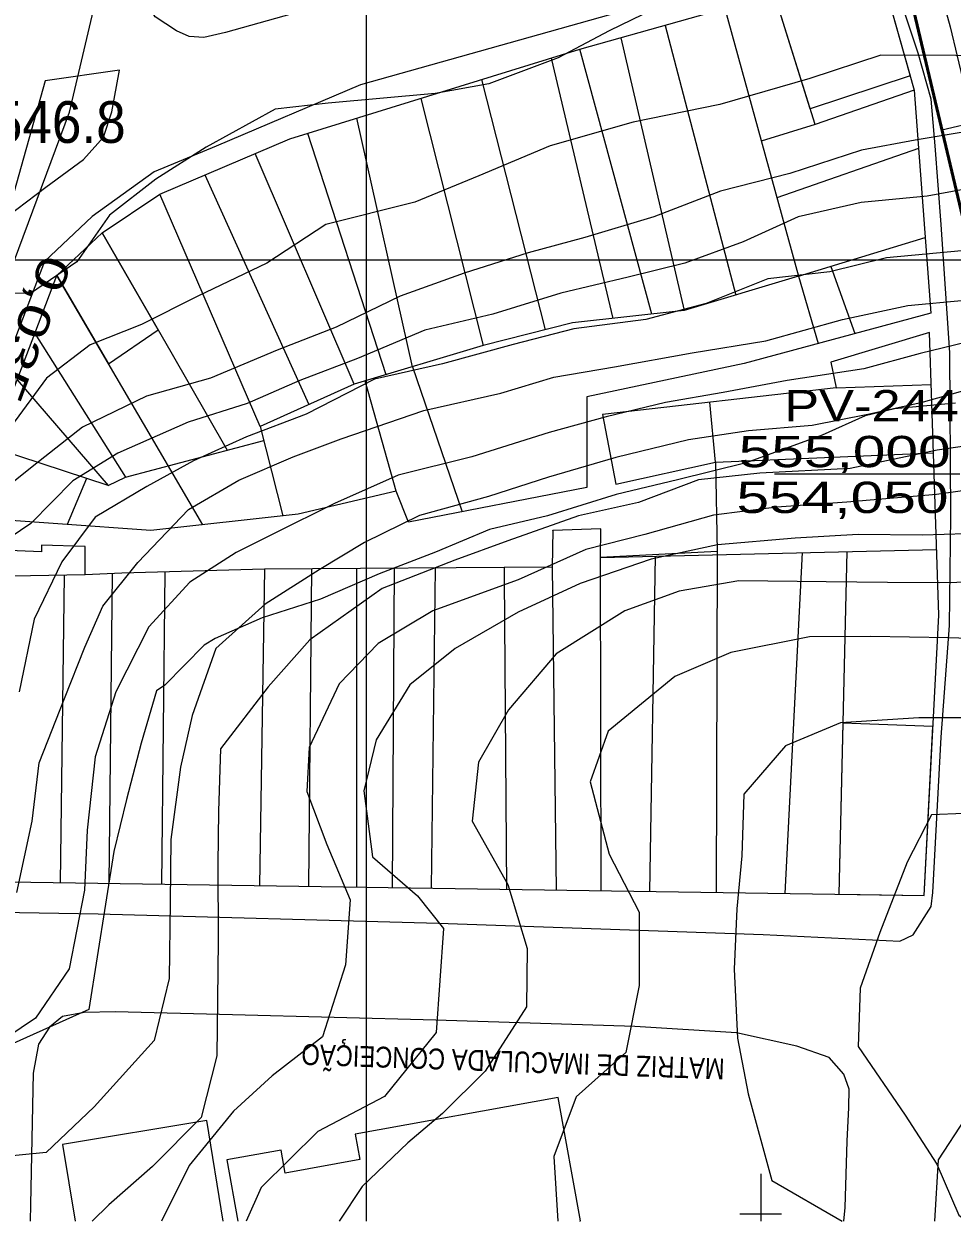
# Model space of a CAD drawing. Extents: x 949 to 2631, y -1701 to -513.
# Drawn here: x 1266.8 to 1355.6, y -912.7 to -798 of the extents above; entities that cross this region are included whole.
import ezdxf

# ---------------------------------------------------------------- set-up
doc = ezdxf.new("R2010")
doc.units = 0
doc.header["$LTSCALE"] = 1.2
for name, color, linetype, lineweight in [('10', 7, 'Continuous', 13), ('11', 7, 'Continuous', 13), ('19', 7, 'Continuous', 13), ('21', 7, 'Continuous', 13), ('29', 7, 'Continuous', 25), ('3', 7, 'Continuous', 13), ('32', 7, 'Continuous', 13), ('33', 7, 'Continuous', 25), ('34', 7, 'Continuous', 35), ('4', 7, 'Continuous', 13), ('5', 7, 'Continuous', 13), ('8', 7, 'Continuous', 13)]:
    doc.layers.add(name, color=color, linetype=linetype, lineweight=lineweight)
doc.layers.add('14', color=7, linetype='Continuous')

msp = doc.modelspace()

# ---------------------------------------------------------------- linework, layer by layer
at = {"layer": '10'}
for p, q in [((1328.142, -798.142), (1334.922, -823.972)), ((1323.902, -799.332), (1329.972, -825.462)), ((1317.232, -801.292), (1323.162, -826.212)), ((1326.872, -825.802), (1320.002, -800.432)), ((1316.692, -827.302), (1310.612, -803.332)), ((1304.772, -805.132), (1310.732, -828.812)), ((1303.972, -830.832), (1298.632, -807.022)), ((1342.512, -807.622), (1337.362, -809.222)), ((1293.912, -808.472), (1301.402, -831.592)), ((1352.412, -809.922), (1338.852, -814.672)), ((1284.082, -812.462), (1294.042, -834.452)), ((1289.382, -836.552), (1279.762, -814.312)), ((1283.892, -845.982), (1269.922, -822.102)), ((1340.912, -822.172), (1342.822, -828.602)), ((1344.032, -821.222), (1346.312, -827.662)), ((1303.972, -830.832), (1308.732, -844.722)), ((1302.402, -842.752), (1299.422, -832.192)), ((1344.542, -832.862), (1353.622, -832.552)), ((1332.992, -839.992), (1332.432, -834.232)), ((1274.812, -842.222), (1263.632, -838.542)), ((1332.992, -839.992), (1353.842, -839.092)), ((1272.752, -841.542), (1270.912, -845.952)), ((1333.122, -848.522), (1333.042, -881.202)), ((1345.562, -848.542), (1344.782, -881.372)), ((1326.692, -881.102), (1327.222, -848.982)), ((1339.652, -881.302), (1341.312, -848.642)), ((1270.622, -850.812), (1270.232, -880.242)), ((1275.212, -850.652), (1274.882, -880.312)), ((1280.242, -850.502), (1279.932, -880.392)), ((1289.782, -850.232), (1289.302, -880.532)), ((1294.292, -850.202), (1294.022, -880.602)), ((1298.642, -880.672), (1298.632, -850.172)), ((1302.212, -850.152), (1302.032, -880.732)), ((1306.122, -850.122), (1305.762, -880.782)), ((1317.352, -850.052), (1317.732, -880.962))]:
    msp.add_line(p, q, dxfattribs=at)
for points in [[(1261.072, -845.232), (1267.812, -827.642), (1269.922, -822.102), (1274.252, -818.022), (1279.762, -814.312), (1292.232, -808.992), (1320.002, -800.432), (1348.632, -792.352), (1351.992, -804.332), (1353.582, -825.712), (1335.712, -830.512), (1320.662, -833.722), (1320.662, -842.402), (1303.592, -845.722), (1302.402, -842.752), (1293.012, -844.962), (1278.902, -846.532)], [(1256.682, -880.042), (1352.952, -881.502), (1354.362, -854.642), (1353.462, -827.572), (1344.032, -830.402), (1344.542, -832.862), (1322.142, -835.402), (1323.442, -842.082), (1332.992, -839.992), (1333.122, -848.522), (1321.962, -849.102), (1321.992, -846.352), (1317.392, -846.522), (1317.392, -846.502), (1317.352, -850.052), (1289.782, -850.232), (1276.142, -850.612), (1272.622, -850.772), (1272.632, -848.042), (1268.442, -847.922), (1268.432, -848.582), (1259.812, -848.222), (1257.372, -854.062), (1257.092, -864.242)]]:
    msp.add_lwpolyline(points, close=True, dxfattribs=at)
for points in [[(1351.992, -804.332), (1342.512, -807.622), (1338.622, -795.182)], [(1333.882, -796.512), (1340.912, -822.172), (1353.042, -818.472)], [(1340.912, -822.172), (1329.972, -825.462), (1319.292, -826.642), (1310.732, -828.812), (1298.392, -832.492), (1288.892, -810.412)], [(1274.252, -818.022), (1280.812, -829.402), (1286.232, -838.832)], [(1267.812, -827.642), (1276.482, -841.402), (1289.722, -837.902)], [(1266.112, -832.082), (1274.812, -842.222), (1276.482, -841.402)], [(1298.392, -832.492), (1289.382, -836.552), (1291.552, -845.122)], [(1322.022, -881.032), (1321.962, -849.102), (1354.152, -848.342)], [(1272.622, -850.772), (1262.132, -850.962), (1261.222, -880.112)], [(1312.982, -880.892), (1312.772, -851.042), (1312.782, -850.082)]]:
    msp.add_lwpolyline(points, dxfattribs=at)
at = {"layer": '11'}
for points in [[(1351.612, -802.972), (1342.042, -806.132), (1338.622, -795.182), (1348.632, -792.352)], [(1269.922, -822.102), (1274.872, -830.572), (1279.602, -827.312), (1274.252, -818.022)], [(1352.952, -881.502), (1353.802, -865.292), (1345.172, -864.982), (1344.782, -881.372)]]:
    msp.add_lwpolyline(points, close=True, dxfattribs=at)
for points in [[(1319.991, -912.671), (1320.042, -912.662), (1317.912, -900.842), (1298.482, -904.342), (1298.922, -906.782), (1291.772, -908.072), (1291.382, -905.872), (1286.182, -906.802), (1287.239, -912.671)], [(1285.842, -912.671), (1284.262, -903.052), (1270.442, -905.322), (1271.649, -912.671)]]:
    msp.add_lwpolyline(points, dxfattribs=at)
at = {"layer": '19'}
for p, q in [((1337.316, -908.149), (1337.312, -912.671)), ((1339.308, -912.02), (1335.301, -912.013))]:
    msp.add_line(p, q, dxfattribs=at)
at = {"layer": '21'}
for p, q in [((1299.562, -912.671), (1299.562, -607.115)), ((1438.974, -820.632), (1228.032, -820.632))]:
    msp.add_line(p, q, dxfattribs=at)
at = {"layer": '29'}
msp.add_line((1354.651, -808.143), (1358.377, -807.261), dxfattribs=at)
at = {"layer": '29', "lineweight": 53}
msp.add_lwpolyline([(1073.88, -805.132), (1073.202, -806.436), (1075.81, -807.79), (1086.799, -786.637), (1101.557, -787.729), (1138.256, -763.647), (1228.052, -719.585), (1284.057, -691.479), (1304.502, -688.949), (1348.513, -782.198), (1360.795, -834.118)], dxfattribs=at)
at = {"layer": '29'}
msp.add_lwpolyline([(1086.799, -786.637), (1101.557, -787.729), (1138.256, -763.647), (1228.052, -719.585), (1284.057, -691.479), (1304.502, -688.949), (1348.513, -782.198), (1360.795, -834.118), (1364.521, -833.237)], dxfattribs=at)
at = {"layer": '32'}
msp.add_lwpolyline([(1254.721, -881.197), (1256.541, -845.637), (1271.121, -806.437), (1289.341, -728.947), (1285.701, -694.297)], dxfattribs=at)
at = {"layer": '33'}
msp.add_line((1356.371, -841.118), (1338.63, -841.118), dxfattribs=at)
at = {"layer": '4'}
for points in [[(1378.512, -810.802), (1376.852, -811.492), (1372.742, -812.462), (1371.602, -812.732), (1365.112, -813.192), (1359.652, -813.332), (1353.232, -814.502), (1346.912, -815.092), (1340.882, -816.492), (1335.632, -818.862), (1330.042, -820.902), (1324.622, -822.252), (1318.182, -823.782), (1311.642, -825.812), (1305.142, -827.332), (1298.702, -830.042), (1293.182, -832.152), (1288.132, -834.362), (1282.492, -836.142), (1275.742, -839.122), (1271.452, -841.772), (1267.422, -845.862), (1262.442, -849.192)], [(1355.959, -834.334), (1350.117, -834.879), (1347.319, -835.529), (1343.185, -837.395), (1335.903, -840.053), (1329.35, -841.685), (1323.464, -843.083), (1316.89, -845.124), (1311.341, -846.421), (1306.153, -848.605), (1300.766, -850.664), (1295.171, -853.112), (1289.562, -854.883), (1285.08, -856.861), (1284.009, -857.523), (1280.235, -861.353), (1279.445, -861.881), (1277.993, -866.881), (1276.575, -872.302), (1275.369, -877.269), (1272.977, -892.4), (1252.838, -901.45)], [(1360.162, -837.972), (1354.212, -838.822), (1345.862, -840.582), (1337.232, -841.042), (1331.352, -841.662), (1325.612, -843.842), (1319.872, -845.122), (1313.102, -847.502), (1308.022, -849.362), (1301.072, -852.072), (1294.122, -856.982), (1290.152, -861.512), (1285.592, -867.432), (1285.392, -873.422), (1285.332, -878.482), (1285.352, -885.782), (1285.292, -891.442), (1285.222, -896.852), (1283.722, -902.762), (1279.072, -907.452), (1274.902, -911.122), (1273.29, -912.671)], [(1359.682, -864.482), (1352.432, -864.472), (1344.942, -864.942), (1339.682, -867.152), (1335.702, -871.782), (1335.502, -877.672), (1335.032, -882.772), (1334.762, -888.532), (1335.072, -895.152), (1336.102, -900.472), (1338.382, -908.792), (1345.114, -912.671)]]:
    msp.add_lwpolyline(points, dxfattribs=at)
at = {"layer": '5'}
for points in [[(1329.252, -795.492), (1322.782, -798.662), (1317.922, -801.252), (1311.282, -803.732), (1306.142, -804.662), (1295.892, -805.592), (1290.812, -806.172), (1284.202, -809.792), (1279.392, -812.872), (1274.942, -816.322), (1271.822, -820.802), (1267.402, -823.812), (1260.302, -823.682)], [(1373.102, -797.892), (1368.652, -800.522), (1361.762, -801.052), (1355.992, -801.032), (1348.812, -800.982), (1342.002, -803.242), (1333.392, -805.722), (1325.082, -807.412), (1317.142, -809.692), (1310.312, -812.552), (1304.182, -815.082), (1295.672, -817.222), (1290.022, -820.902), (1283.402, -824.092), (1278.002, -826.792), (1273.092, -828.752), (1268.922, -831.942), (1265.482, -836.612)], [(1359.942, -807.822), (1352.102, -809.122), (1346.952, -810.102), (1340.082, -812.312), (1333.462, -814.032), (1327.082, -816.482), (1320.452, -818.452), (1315.052, -819.922), (1308.922, -821.882), (1302.782, -824.092), (1296.652, -827.042), (1291.002, -829.242), (1284.622, -831.942), (1278.492, -833.662), (1272.352, -836.612), (1267.692, -840.292), (1262.782, -844.212)], [(1359.282, -819.482), (1349.352, -820.392), (1343.932, -821.742), (1338.002, -822.422), (1332.072, -824.792), (1326.312, -826.322), (1319.422, -827.202), (1313.612, -828.692), (1306.852, -830.552), (1300.342, -832.042), (1293.772, -835.382), (1288.062, -837.542), (1283.002, -839.842), (1278.542, -842.322), (1273.572, -845.232), (1270.402, -849.532), (1267.742, -855.022), (1266.312, -861.992)], [(1266.082, -881.212), (1267.542, -874.362), (1268.222, -868.782), (1270.642, -862.622), (1272.602, -857.712), (1274.322, -853.782), (1277.662, -849.602), (1282.512, -844.502), (1287.332, -841.702), (1292.532, -839.472), (1297.122, -837.742), (1305.042, -835.022), (1312.412, -833.372), (1317.482, -831.852), (1323.312, -830.842), (1330.732, -829.502), (1337.812, -828.342), (1345.122, -826.322), (1351.392, -824.962), (1356.852, -824.452)], [(1359.262, -827.932), (1352.582, -829.562), (1347.172, -831.052), (1339.852, -832.162), (1333.702, -833.312), (1328.202, -834.272), (1322.512, -835.632), (1317.062, -837.122), (1309.632, -839.472), (1302.592, -841.232), (1296.492, -843.942), (1290.732, -846.822), (1287.082, -848.642), (1282.632, -851.482), (1278.732, -855.752), (1275.552, -861.972), (1273.582, -868.202), (1272.812, -875.242), (1272.572, -880.982), (1271.102, -888.522), (1267.862, -893.232), (1262.452, -896.892)], [(1359.362, -832.422), (1352.652, -834.282), (1347.562, -835.422), (1342.242, -836.482), (1336.142, -836.992), (1330.382, -837.842), (1323.432, -839.532), (1316.992, -841.402), (1311.232, -843.262), (1304.642, -845.092), (1299.372, -847.682), (1295.032, -850.292), (1289.862, -853.592), (1285.142, -857.832), (1282.852, -864.232), (1281.742, -869.192), (1280.822, -876.132), (1280.752, -882.102), (1280.662, -889.422), (1279.222, -895.382), (1273.472, -901.742), (1268.882, -906.102), (1263.692, -906.602)], [(1360.282, -842.202), (1354.132, -843.082), (1345.542, -843.812), (1338.852, -844.282), (1332.792, -845.042), (1326.222, -846.902), (1320.552, -848.342), (1314.082, -851.242), (1305.912, -854.212), (1300.692, -857.352), (1296.952, -861.212), (1294.072, -867.302), (1293.862, -871.532), (1295.762, -876.602), (1297.982, -881.892), (1297.562, -888.132), (1295.332, -895.012), (1290.512, -898.752), (1286.822, -902.132), (1282.572, -907.362), (1279.945, -912.671)], [(1359.012, -846.792), (1352.812, -846.972), (1346.632, -846.892), (1340.592, -847.272), (1333.162, -847.892), (1326.822, -849.262), (1320.032, -851.612), (1314.082, -854.332), (1308.062, -857.822), (1303.712, -861.292), (1300.482, -866.582), (1299.302, -871.452), (1300.122, -877.782), (1304.442, -881.512), (1306.922, -884.632), (1306.222, -894.612), (1301.282, -900.742), (1294.912, -904.092), (1289.472, -909.472), (1288.044, -912.671)], [(1359.322, -851.452), (1354.472, -851.532), (1349.442, -851.502), (1343.572, -851.452), (1335.222, -851.332), (1329.492, -852.332), (1324.292, -854.212), (1317.732, -858.342), (1313.152, -863.702), (1310.282, -868.722), (1309.662, -874.382), (1313.082, -880.442), (1314.952, -886.562), (1314.892, -892.152), (1310.912, -898.302), (1306.822, -902.382), (1303.532, -905.182), (1299.142, -909.372), (1296.94, -912.671)], [(1362.292, -857.042), (1355.282, -856.802), (1347.822, -856.682), (1341.972, -856.722), (1334.432, -858.212), (1329.092, -860.522), (1322.702, -865.752), (1320.982, -870.612), (1322.792, -877.522), (1325.662, -883.092), (1325.682, -890.112), (1324.382, -896.532), (1319.642, -900.782), (1317.482, -906.502), (1317.887, -912.671)], [(1438.974, -884.394), (1433.602, -881.622), (1422.692, -878.042), (1417.792, -876.432), (1409.672, -874.162), (1403.702, -872.502), (1397.722, -871.112), (1389.032, -869.382), (1381.082, -868.732), (1375.252, -868.652), (1369.022, -869.382), (1359.862, -873.512), (1353.672, -873.752), (1351.322, -878.292), (1348.722, -885.022), (1346.842, -890.362), (1346.622, -895.952), (1351.142, -902.512), (1354.172, -907.222), (1356.262, -912.122), (1357.054, -912.671)]]:
    msp.add_lwpolyline(points, dxfattribs=at)
at = {"layer": '8'}
for points in [[(1336.322, -745.502), (1347.332, -772.682), (1349.352, -777.042), (1350.432, -778.482), (1351.772, -779.272), (1353.892, -779.292), (1389.292, -768.962), (1393.382, -768.602), (1397.262, -768.472), (1399.172, -775.642), (1366.552, -784.062), (1353.192, -789.082), (1353.182, -790.002), (1355.462, -798.272), (1360.132, -817.952), (1363.272, -828.742), (1363.812, -830.352), (1364.322, -831.052), (1365.312, -831.522), (1372.842, -831.172), (1410.152, -827.372), (1438.974, -824.574)], [(1331.712, -746.692), (1345.172, -778.472), (1345.822, -779.662), (1345.682, -780.902), (1343.832, -781.952), (1311.812, -791.562), (1286.072, -798.812), (1283.992, -799.302), (1282.572, -799.202), (1281.372, -798.652), (1279.322, -797.332), (1278.822, -796.482)], [(1258.762, -883.002), (1273.872, -883.252), (1306.462, -884.142), (1337.542, -885.222), (1350.632, -885.862), (1351.892, -885.242), (1353.632, -882.532), (1353.772, -881.202), (1354.582, -866.332), (1355.372, -855.622), (1355.502, -845.162), (1355.422, -829.492), (1354.572, -817.202), (1354.022, -809.662), (1353.622, -805.222), (1352.392, -800.792), (1349.112, -791.032)], [(1323.742, -796.882), (1298.982, -803.842), (1285.172, -809.702), (1279.222, -812.182), (1273.282, -816.432), (1268.732, -820.762), (1259.522, -844.752)], [(1345.259, -912.671), (1345.402, -911.372), (1345.582, -905.022), (1345.742, -901.782), (1345.772, -900.052), (1345.272, -898.592), (1343.862, -897.012), (1340.762, -895.932), (1334.982, -894.642), (1325.262, -894.042), (1306.202, -893.432), (1286.732, -892.902), (1275.502, -892.642), (1272.512, -892.702), (1270.462, -893.092), (1269.202, -894.102), (1268.162, -895.742), (1267.642, -898.492), (1267.392, -911.072), (1267.36, -912.671)], [(1380.107, -912.671), (1380.112, -912.192), (1379.932, -910.042), (1378.982, -908.302), (1377.552, -906.752), (1375.822, -905.662), (1372.362, -904.442), (1364.912, -902.522), (1362.162, -901.792), (1359.682, -901.662), (1356.892, -902.862), (1354.312, -906.812), (1353.946, -912.671)]]:
    msp.add_lwpolyline(points, dxfattribs=at)
msp.add_lwpolyline([(1265.162, -816.462), (1268.842, -813.642), (1272.472, -810.982), (1274.362, -808.862), (1275.182, -806.422), (1275.922, -802.422), (1268.782, -803.462)], close=True, dxfattribs=at)

# ---------------------------------------------------------------- texts
at = {"layer": '14', "width": 0.85}
msp.add_text('MATRIZ DE IMACULADA CONCEIÇÃO', height=2, rotation=178, dxfattribs=at).set_placement((1333.882, -897.112))
at = {"layer": '3', "width": 0.95}
msp.add_text('546.8', height=4, dxfattribs=at).set_placement((1263.785, -809.399))
at = {"layer": '33'}
for s, width, p in [('PV-244', 1.25, (1339.556, -836.067)), (' 555,000', 1.4, (1333.636, -840.462)), (' 554,050', 1.4, (1333.426, -844.85))]:
    msp.add_text(s, height=3, dxfattribs=dict(at, width=width)).set_placement(p)
at = {"layer": '34', "width": 1.45}
msp.add_text('0,03587', height=3, rotation=249.598, dxfattribs=at).set_placement((1268.559, -819.897))

doc.saveas('drawing.dxf')
